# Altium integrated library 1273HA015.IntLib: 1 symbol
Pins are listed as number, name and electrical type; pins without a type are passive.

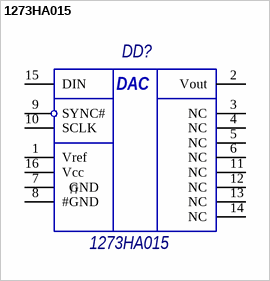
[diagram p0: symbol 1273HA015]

## 1273HA015
designator DD?
footprint PCBComponent_1
pins: 1 Vref, 2 Vout, 3 NC, 4 NC, 5 NC, 6 NC, 7   GND, 8 #GND, 9 SYNC#, 10 SCLK, 11 NC, 12 NC, 13 NC, 14 NC, 15 DIN, 16 Vcc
